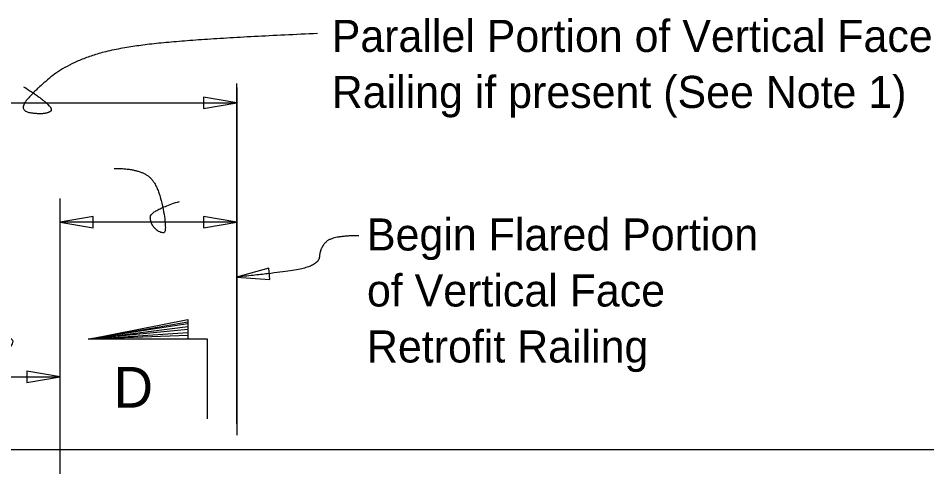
# Model space of a CAD drawing. Extents: x 1.5 to 68.7, y 0 to 31.1.
# Drawn here: x 28.44 to 34.15, y 13.67 to 16.53 of the extents above; entities that cross this region are included whole.
import ezdxf

# ---------------------------------------------------------------- set-up
doc = ezdxf.new("R2010")
doc.units = 0
for name, color, linetype in [('Dimension', 7, 'Continuous'), ('TextStructures', 7, 'Continuous'), ('TrafBarrierConc', 7, 'Continuous')]:
    doc.layers.add(name, color=color, linetype=linetype)

msp = doc.modelspace()

# ---------------------------------------------------------------- linework, layer by layer
at = {"layer": 'Dimension'}
for p, q in [((29.8106, 13.981), (29.8106, 16.1198)), ((29.8106, 16.0948), (29.8106, 13.9093)), ((28.7009, 13.6663), (28.7009, 15.3961)), ((29.8106, 15.2478), (28.7009, 15.2478)), ((28.878, 14.5119), (29.503, 14.6219)), ((29.503, 14.6085), (28.878, 14.5119)), ((28.878, 14.5119), (29.503, 14.5919)), ((29.503, 14.5735), (28.878, 14.5119)), ((28.878, 14.5119), (29.503, 14.5552)), ((29.503, 14.5352), (28.878, 14.5119))]:
    msp.add_line(p, q, dxfattribs=at)
for points in [[(26.2771, 15.9978), (29.8106, 15.9978)], [(29.628, 14.0119), (29.628, 14.5119), (28.878, 14.5119), (29.503, 14.6369), (29.503, 14.5119)]]:
    msp.add_lwpolyline(points, dxfattribs=at)
for points in [[(29.8106, 15.9978), (29.6024, 16.0331), (29.6024, 15.9626)], [(28.7009, 15.2478), (28.9091, 15.2126), (28.9091, 15.2831)], [(29.8106, 15.2478), (29.6024, 15.2831), (29.6024, 15.2126)], [(29.8085, 14.903), (30.0192, 14.8883), (30.0123, 14.9585)], [(28.7009, 14.2766), (28.4926, 14.3119), (28.4926, 14.2413)]]:
    msp.add_lwpolyline(points, close=True, dxfattribs=at)
for points in [[(30.3185, 16.4334), (29.7625, 16.41), (29.085, 16.3539), (28.7533, 16.2464), (28.5617, 16.0968), (28.4309, 15.9472), (28.6131, 15.9239), (28.6738, 15.9706), (28.4729, 16.0968)], [(29.0412, 15.5861), (29.189, 15.5861), (29.3172, 15.4924), (29.3763, 15.1816), (29.3221, 15.1816), (29.2679, 15.2408), (29.2679, 15.3197), (29.4502, 15.3789)], [(30.5774, 15.1629), (30.4111, 15.1629), (30.3332, 15.0849), (30.328, 14.9809), (30.1253, 14.9341), (29.8084, 14.903)], [(27.8361, 14.5528), (28.0726, 14.5528), (28.3289, 14.5528), (28.4472, 14.4862), (28.1022, 14.2766), (28.4398, 14.2766), (28.7009, 14.2766)]]:
    msp.add_open_spline(points, degree=2, dxfattribs=at)
at = {"layer": 'TrafBarrierConc'}
msp.add_line((36.5515, 13.8178), (26.2771, 13.8178), dxfattribs=at)

# ---------------------------------------------------------------- texts
at = {"layer": 'Dimension'}
for s, p in [('Parallel Portion of Vertical Face Retrofit ', (30.4075, 16.3181)), ('Railing if present (See Note 1)', (30.4075, 15.9661)), ('Begin Flared Portion ', (30.629, 15.0701)), ('of Vertical Face ', (30.629, 14.7181)), ('Retrofit Railing', (30.629, 14.3661))]:
    msp.add_text(s, height=0.2016, dxfattribs=at).set_placement(p)
at = {"layer": 'TextStructures'}
msp.add_text('D', height=0.256, dxfattribs=at).set_placement((29.0376, 14.0824))

doc.saveas('drawing.dxf')
